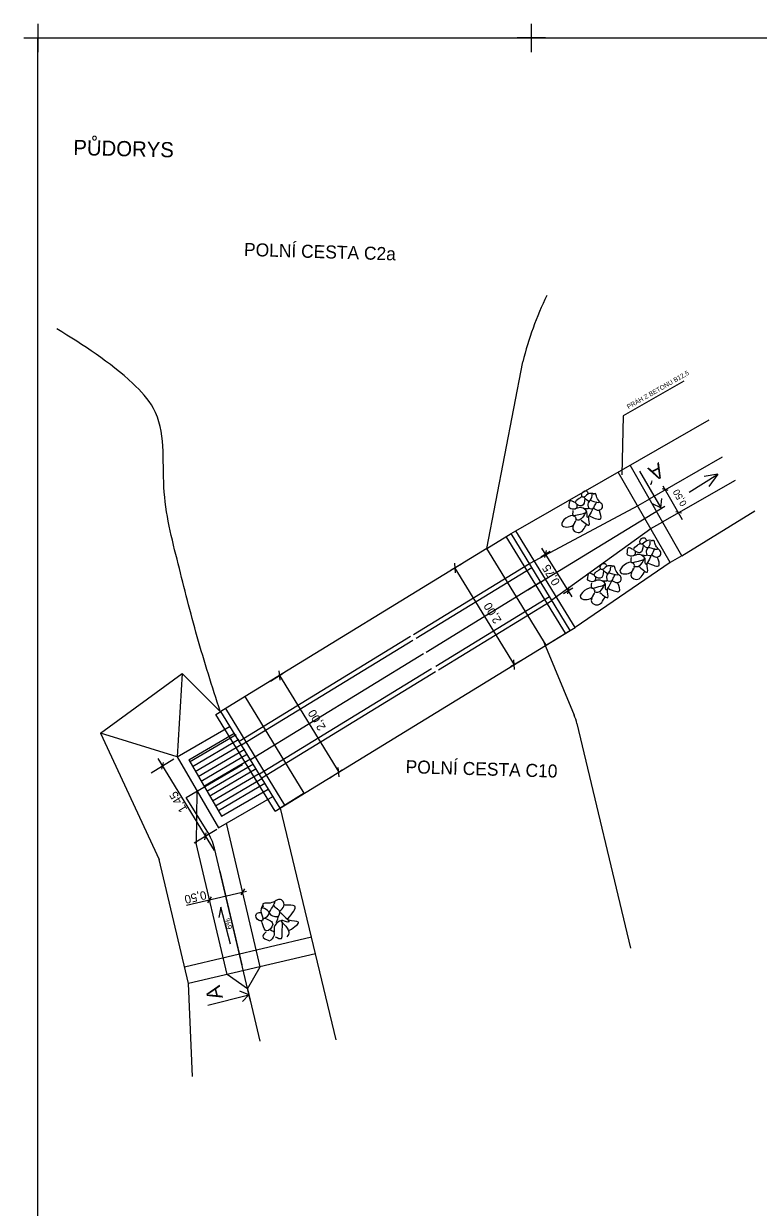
# Model space of a CAD drawing. Extents: x -463095.2 to -463031, y -1105061.3 to -1104976.3.
# Drawn here: x -463091.37 to -463065.46, y -1105018.06 to -1104976.31 of the extents above; entities that cross this region are included whole.
import ezdxf

# ---------------------------------------------------------------- set-up
doc = ezdxf.new("R2010")
doc.units = 0
for name, color, linetype in [('Implicitní', 7, 'Continuous'), ('Vrstva 14', 7, 'Continuous'), ('Vrstva 57', 7, 'Continuous')]:
    doc.layers.add(name, color=color, linetype=linetype)

msp = doc.modelspace()

# ---------------------------------------------------------------- linework, layer by layer
at = {"layer": 'Implicitní'}
for p, q in [((-463073.467, -1104976.311), (-463073.467, -1104977.311)), ((-463073.467, -1104976.311), (-463073.467, -1104977.311)), ((-463073.467, -1104976.312), (-463073.467, -1104977.312)), ((-463073.467, -1104976.312), (-463073.467, -1104977.312)), ((-463072.967, -1104976.811), (-463073.967, -1104976.811)), ((-463072.967, -1104976.811), (-463073.967, -1104976.811)), ((-463072.967, -1104976.812), (-463073.967, -1104976.812)), ((-463072.967, -1104976.812), (-463073.967, -1104976.812))]:
    msp.add_line(p, q, dxfattribs=at)
at = {"layer": 'Vrstva 14'}
for p, q in [((-463090.867, -1104976.311), (-463090.867, -1104977.311)), ((-463090.867, -1104976.312), (-463090.867, -1104977.312)), ((-463090.867, -1104976.312), (-463090.867, -1104977.312)), ((-463091.367, -1104976.811), (-463090.367, -1104976.811)), ((-463091.367, -1104976.812), (-463090.367, -1104976.812)), ((-463091.367, -1104976.812), (-463090.367, -1104976.812)), ((-463075.036, -1104994.821), (-463073.77, -1104988.236)), ((-463068.091, -1104988.92), (-463070.232, -1104990.146)), ((-463070.232, -1104990.146), (-463070.28, -1104992.219)), ((-463074.013, -1104994.194), (-463067.196, -1104990.29)), ((-463069.301, -1104993.076), (-463066.73, -1104991.595)), ((-463068.574, -1104995.32), (-463070.403, -1104992.127)), ((-463068.157, -1104995.081), (-463069.987, -1104991.888)), ((-463067.903, -1104992.83), (-463066.894, -1104992.206)), ((-463066.894, -1104992.206), (-463067.377, -1104992.28)), ((-463066.894, -1104992.206), (-463067.208, -1104992.63)), ((-463068.842, -1104993.886), (-463066.262, -1104992.412)), ((-463068.827, -1104992.607), (-463068.143, -1104993.801)), ((-463068.906, -1104993.389), (-463068.87, -1104993.054)), ((-463068.645, -1104992.771), (-463068.836, -1104992.718)), ((-463069.714, -1104993.315), (-463073.521, -1104995.347)), ((-463069.297, -1104993.077), (-463069.714, -1104993.315)), ((-463068.843, -1104993.889), (-463069.26, -1104994.127)), ((-463068.176, -1104993.579), (-463068.367, -1104993.526)), ((-463068.157, -1104995.081), (-463065.582, -1104993.499)), ((-463075.036, -1104994.821), (-463074.183, -1104994.299)), ((-463074.183, -1104994.299), (-463074.013, -1104994.194)), ((-463072.093, -1104997.709), (-463074.183, -1104994.299)), ((-463071.923, -1104997.605), (-463074.013, -1104994.194)), ((-463069.252, -1104994.123), (-463072.748, -1104996.647)), ((-463072.264, -1104997.814), (-463074.354, -1104994.403)), ((-463075.036, -1104994.821), (-463083.563, -1105000.046)), ((-463072.946, -1104998.232), (-463075.036, -1104994.821)), ((-463073.132, -1104995.117), (-463072.802, -1104994.913)), ((-463072.032, -1104996.532), (-463073.093, -1104994.815)), ((-463072.949, -1104994.895), (-463073.004, -1104995.137)), ((-463068.157, -1104995.081), (-463068.574, -1104995.32)), ((-463077.618, -1104997.858), (-463073.535, -1104995.356)), ((-463077.526, -1104997.989), (-463073.452, -1104995.492)), ((-463075.931, -1104995.37), (-463076.291, -1104995.59)), ((-463076.178, -1104995.345), (-463076.149, -1104995.679)), ((-463076.163, -1104995.512), (-463074.073, -1104998.923)), ((-463068.574, -1104995.32), (-463071.923, -1104997.605)), ((-463077.18, -1104998.481), (-463073.138, -1104996.004)), ((-463072.333, -1104996.41), (-463072.003, -1104996.206)), ((-463072.14, -1104996.178), (-463072.196, -1104996.419)), ((-463076.836, -1104998.973), (-463072.825, -1104996.516)), ((-463076.744, -1104999.105), (-463072.741, -1104996.652)), ((-463072.093, -1104997.709), (-463071.923, -1104997.605)), ((-463077.731, -1104997.927), (-463083.767, -1105001.626)), ((-463077.647, -1104998.063), (-463083.684, -1105001.762)), ((-463082.496, -1105004.084), (-463072.085, -1104997.704)), ((-463072.946, -1104998.232), (-463072.093, -1104997.709)), ((-463073.024, -1104998.124), (-463071.957, -1105000.697)), ((-463077.274, -1104998.538), (-463083.37, -1105002.274)), ((-463073.841, -1104998.78), (-463074.201, -1104999.001)), ((-463074.059, -1104999.09), (-463074.088, -1104998.755)), ((-463088.659, -1105001.332), (-463085.777, -1104999.23)), ((-463085.777, -1104999.23), (-463085.957, -1105002.169)), ((-463084.438, -1105000.57), (-463085.777, -1104999.23)), ((-463076.989, -1104999.067), (-463083.057, -1105002.785)), ((-463076.846, -1104999.167), (-463082.973, -1105002.922)), ((-463082.667, -1104999.497), (-463082.222, -1104999.224)), ((-463082.365, -1104999.136), (-463082.336, -1104999.47)), ((-463082.35, -1104999.303), (-463080.26, -1105002.714)), ((-463083.563, -1105000.046), (-463084.415, -1105000.568)), ((-463081.473, -1105003.456), (-463083.563, -1105000.046)), ((-463084.586, -1105000.673), (-463084.415, -1105000.568)), ((-463082.325, -1105003.979), (-463084.415, -1105000.568)), ((-463082.155, -1105003.874), (-463084.245, -1105000.464)), ((-463082.496, -1105004.083), (-463084.586, -1105000.673)), ((-463071.859, -1105000.999), (-463069.969, -1105008.921)), ((-463088.659, -1105001.332), (-463086.589, -1105005.788)), ((-463085.957, -1105002.169), (-463088.659, -1105001.332)), ((-463085.957, -1105002.169), (-463084.085, -1105001.084)), ((-463085.547, -1105002.278), (-463083.952, -1105001.353)), ((-463083.878, -1105001.39), (-463085.519, -1105002.357)), ((-463083.777, -1105001.563), (-463085.417, -1105002.529)), ((-463083.675, -1105001.735), (-463085.316, -1105002.702)), ((-463086.074, -1105002.258), (-463086.873, -1105002.747)), ((-463086.642, -1105002.23), (-463084.653, -1105005.477)), ((-463085.957, -1105002.169), (-463084.502, -1105004.678)), ((-463083.574, -1105001.907), (-463085.214, -1105002.874)), ((-463083.472, -1105002.08), (-463085.113, -1105003.046)), ((-463083.371, -1105002.252), (-463085.011, -1105003.219)), ((-463086.496, -1105002.607), (-463086.439, -1105002.366)), ((-463085.547, -1105002.278), (-463084.393, -1105004.268)), ((-463083.269, -1105002.424), (-463084.91, -1105003.391)), ((-463083.167, -1105002.596), (-463084.808, -1105003.563)), ((-463080.577, -1105002.908), (-463080.132, -1105002.635)), ((-463080.246, -1105002.881), (-463080.275, -1105002.546)), ((-463083.066, -1105002.769), (-463084.706, -1105003.736)), ((-463082.964, -1105002.941), (-463084.605, -1105003.908)), ((-463082.863, -1105003.113), (-463084.503, -1105004.08)), ((-463084.393, -1105004.268), (-463082.745, -1105003.312)), ((-463081.473, -1105003.456), (-463082.325, -1105003.979)), ((-463084.502, -1105004.678), (-463082.587, -1105003.567)), ((-463082.496, -1105004.083), (-463082.325, -1105003.979)), ((-463082.329, -1105003.983), (-463080.355, -1105012.151)), ((-463084.559, -1105004.73), (-463085.357, -1105005.219)), ((-463084.985, -1105005.096), (-463084.928, -1105004.855)), ((-463083.367, -1105010.789), (-463084.644, -1105005.396)), ((-463083.661, -1105009.504), (-463084.435, -1105006.208)), ((-463083.582, -1105006.829), (-463083.714, -1105007.039)), ((-463085.623, -1105007.407), (-463083.516, -1105006.912)), ((-463084.759, -1105007.112), (-463084.89, -1105007.322)), ((-463081.218, -1105008.531), (-463085.696, -1105009.584)), ((-463081.081, -1105009.117), (-463085.559, -1105010.17)), ((-463083.43, -1105010.56), (-463083.744, -1105010.437)), ((-463083.47, -1105010.349), (-463083.043, -1105012.2))]:
    msp.add_line(p, q, dxfattribs=at)
msp.add_lwpolyline([(-463090.867, -1105060.811), (-463090.867, -1104976.812), (-463031.467, -1104976.812), (-463031.467, -1105060.811)], close=True, dxfattribs=at)
for points in [[(-463069.649, -1104992.092), (-463068.906, -1104993.389), (-463069.199, -1104993.243)], [(-463073.59, -1104996.283), (-463068.761, -1104993.331)], [(-463084.894, -1105004.797), (-463085.635, -1105003.611), (-463083.657, -1105002.446)], [(-463085.262, -1105003.375), (-463085.259, -1105003.378), (-463085.284, -1105005.221)], [(-463083.47, -1105010.349), (-463083.027, -1105009.576), (-463084.218, -1105004.512)], [(-463083.47, -1105010.349), (-463084.195, -1105009.845), (-463085.284, -1105005.221)], [(-463085.419, -1105013.452), (-463085.559, -1105010.17), (-463086.589, -1105005.788)], [(-463084.075, -1105008.775), (-463084.415, -1105007.469), (-463084.487, -1105007.843)], [(-463084.877, -1105010.935), (-463083.43, -1105010.56), (-463083.648, -1105010.804)]]:
    msp.add_lwpolyline(points, dxfattribs=at)
for centre, radius, start, end in [((-463061.322, -1104991.416), 12.848, 154.5646, 165.6667), ((-463073.805, -1105001.463), 2, 13.4219, 22.5132), ((-463086.59, -1105005.857), 2, 13.3222, 31.992)]:
    msp.add_arc(centre, radius, start, end, dxfattribs=at)
for points in [[(-463084.438, -1105000.57), (-463085.247, -1104997.939), (-463085.919, -1104995.363), (-463086.422, -1104992.659), (-463086.79, -1104989.879), (-463087.515, -1104989.004), (-463090.196, -1104987.076)], [(-463071.579, -1104993.056), (-463071.691, -1104993.318), (-463071.909, -1104993.202), (-463071.778, -1104993.05), (-463071.676, -1104992.981)], [(-463071.237, -1104992.893), (-463071.47, -1104992.907), (-463071.65, -1104993.01), (-463071.693, -1104992.915), (-463071.536, -1104992.791), (-463071.458, -1104992.889)], [(-463071.625, -1104992.996), (-463071.405, -1104993.132), (-463071.326, -1104992.967), (-463071.325, -1104992.911)], [(-463071.389, -1104993.122), (-463071.064, -1104993.176), (-463071.154, -1104993.021), (-463071.208, -1104992.887), (-463071.291, -1104992.913)], [(-463071.943, -1104993.2), (-463072.086, -1104993.14), (-463072.149, -1104993.371)], [(-463071.857, -1104993.293), (-463071.88, -1104993.404), (-463072.078, -1104993.419), (-463072.144, -1104993.38)], [(-463071.999, -1104993.483), (-463071.992, -1104993.665), (-463071.854, -1104993.639), (-463071.527, -1104993.508), (-463071.696, -1104993.384), (-463071.884, -1104993.417)], [(-463071.289, -1104993.393), (-463071.499, -1104993.709), (-463071.509, -1104993.519), (-463071.755, -1104993.811), (-463071.904, -1104993.799)], [(-463071.602, -1104993.397), (-463071.441, -1104993.392), (-463071.464, -1104993.296), (-463071.401, -1104993.14)], [(-463071.469, -1104993.393), (-463071.267, -1104993.392), (-463071.234, -1104993.318), (-463071.153, -1104993.173)], [(-463071.406, -1104993.683), (-463071.017, -1104993.767), (-463071.069, -1104993.49)], [(-463071.277, -1104993.392), (-463071.102, -1104993.471), (-463070.96, -1104993.378), (-463070.965, -1104993.272), (-463071.073, -1104993.177)], [(-463071.876, -1104993.772), (-463071.952, -1104993.671), (-463072.394, -1104993.997), (-463071.996, -1104994.003), (-463071.913, -1104993.865)], [(-463071.894, -1104993.836), (-463071.985, -1104994.177), (-463071.813, -1104994.258), (-463071.516, -1104993.962)], [(-463071.709, -1104993.818), (-463071.422, -1104993.993), (-463071.439, -1104993.719), (-463071.43, -1104993.658)], [(-463069.526, -1104994.71), (-463069.638, -1104994.971), (-463069.855, -1104994.856), (-463069.724, -1104994.704), (-463069.622, -1104994.634)], [(-463069.184, -1104994.547), (-463069.416, -1104994.56), (-463069.596, -1104994.664), (-463069.64, -1104994.569), (-463069.482, -1104994.445), (-463069.404, -1104994.542)], [(-463069.571, -1104994.649), (-463069.351, -1104994.785), (-463069.273, -1104994.62), (-463069.272, -1104994.564)], [(-463069.335, -1104994.776), (-463069.011, -1104994.83), (-463069.1, -1104994.674), (-463069.154, -1104994.541), (-463069.237, -1104994.567)], [(-463069.889, -1104994.854), (-463070.033, -1104994.794), (-463070.095, -1104995.025)], [(-463069.803, -1104994.946), (-463069.826, -1104995.057), (-463070.024, -1104995.073), (-463070.091, -1104995.033)], [(-463069.945, -1104995.136), (-463069.938, -1104995.319), (-463069.8, -1104995.293), (-463069.474, -1104995.161), (-463069.642, -1104995.038), (-463069.83, -1104995.07)], [(-463069.235, -1104995.047), (-463069.445, -1104995.362), (-463069.456, -1104995.173), (-463069.701, -1104995.465), (-463069.851, -1104995.453)], [(-463069.548, -1104995.051), (-463069.387, -1104995.045), (-463069.41, -1104994.95), (-463069.347, -1104994.794)], [(-463069.416, -1104995.047), (-463069.213, -1104995.045), (-463069.18, -1104994.971), (-463069.099, -1104994.827)], [(-463069.353, -1104995.337), (-463068.964, -1104995.421), (-463069.015, -1104995.144)], [(-463069.223, -1104995.045), (-463069.048, -1104995.124), (-463068.906, -1104995.032), (-463068.911, -1104994.926), (-463069.019, -1104994.831)], [(-463070.923, -1104995.61), (-463071.035, -1104995.872), (-463071.252, -1104995.757), (-463071.122, -1104995.605), (-463071.02, -1104995.535)], [(-463070.581, -1104995.448), (-463070.813, -1104995.461), (-463070.994, -1104995.564), (-463071.037, -1104995.469), (-463070.879, -1104995.346), (-463070.801, -1104995.443)], [(-463070.969, -1104995.55), (-463070.749, -1104995.686), (-463070.67, -1104995.521), (-463070.669, -1104995.465)], [(-463070.732, -1104995.676), (-463070.408, -1104995.73), (-463070.497, -1104995.575), (-463070.551, -1104995.442), (-463070.634, -1104995.467)], [(-463069.822, -1104995.425), (-463069.898, -1104995.325), (-463070.34, -1104995.65), (-463069.942, -1104995.656), (-463069.859, -1104995.518)], [(-463069.841, -1104995.489), (-463069.931, -1104995.831), (-463069.759, -1104995.911), (-463069.462, -1104995.616)], [(-463069.655, -1104995.472), (-463069.369, -1104995.647), (-463069.386, -1104995.373), (-463069.376, -1104995.312)], [(-463071.287, -1104995.754), (-463071.43, -1104995.694), (-463071.493, -1104995.926)], [(-463071.201, -1104995.847), (-463071.224, -1104995.958), (-463071.421, -1104995.973), (-463071.488, -1104995.934)], [(-463071.343, -1104996.037), (-463071.336, -1104996.219), (-463071.198, -1104996.194), (-463070.871, -1104996.062), (-463071.039, -1104995.939), (-463071.227, -1104995.971)], [(-463070.632, -1104995.947), (-463070.842, -1104996.263), (-463070.853, -1104996.074), (-463071.099, -1104996.366), (-463071.248, -1104996.353)], [(-463070.945, -1104995.951), (-463070.784, -1104995.946), (-463070.808, -1104995.85), (-463070.744, -1104995.694)], [(-463070.813, -1104995.948), (-463070.611, -1104995.946), (-463070.578, -1104995.872), (-463070.496, -1104995.728)], [(-463070.62, -1104995.946), (-463070.446, -1104996.025), (-463070.304, -1104995.932), (-463070.309, -1104995.827), (-463070.417, -1104995.732)], [(-463071.219, -1104996.326), (-463071.295, -1104996.226), (-463071.738, -1104996.551), (-463071.34, -1104996.557), (-463071.256, -1104996.419)], [(-463071.238, -1104996.39), (-463071.328, -1104996.731), (-463071.157, -1104996.812), (-463070.86, -1104996.516)], [(-463071.053, -1104996.372), (-463070.766, -1104996.548), (-463070.783, -1104996.273), (-463070.774, -1104996.213)], [(-463070.75, -1104996.238), (-463070.361, -1104996.321), (-463070.413, -1104996.045)], [(-463082.349, -1105007.618), (-463082.193, -1105007.437), (-463082.253, -1105007.234), (-463082.381, -1105007.202), (-463082.534, -1105007.298)], [(-463082.932, -1105007.393), (-463082.999, -1105007.676), (-463082.94, -1105007.929), (-463083.069, -1105007.947), (-463083.161, -1105007.714), (-463083.016, -1105007.656)], [(-463082.948, -1105007.894), (-463082.707, -1105007.679), (-463082.876, -1105007.526), (-463082.943, -1105007.505)], [(-463082.712, -1105007.656), (-463082.532, -1105007.287), (-463082.75, -1105007.338), (-463082.929, -1105007.356), (-463082.928, -1105007.464)], [(-463082.459, -1105008.009), (-463082.408, -1105007.815), (-463082.531, -1105007.808), (-463082.695, -1105007.677)], [(-463082.416, -1105007.849), (-463082.346, -1105007.607), (-463082.423, -1105007.541), (-463082.567, -1105007.392)], [(-463082.352, -1105007.633), (-463082.049, -1105007.997), (-463082.279, -1105007.942), (-463082.017, -1105008.341), (-463082.085, -1105008.515)], [(-463082.046, -1105007.877), (-463081.807, -1105007.441), (-463082.157, -1105007.404)], [(-463082.859, -1105007.861), (-463082.586, -1105008.089), (-463082.802, -1105008.308), (-463082.937, -1105008.097), (-463082.984, -1105007.95)], [(-463082.498, -1105008.516), (-463082.277, -1105008.573), (-463082.258, -1105008.398), (-463082.3, -1105007.96), (-463082.507, -1105008.117), (-463082.536, -1105008.354)], [(-463081.993, -1105008.288), (-463081.681, -1105008.007), (-463082.015, -1105007.93), (-463082.085, -1105007.897)], [(-463082.817, -1105008.348), (-463082.94, -1105008.498), (-463082.685, -1105008.656)], [(-463082.675, -1105008.278), (-463082.55, -1105008.345), (-463082.602, -1105008.587), (-463082.673, -1105008.653)]]:
    msp.add_spline(points, degree=3, dxfattribs=at)

# ---------------------------------------------------------------- texts
for s, height, rotation, p in [('PŮDORYS', 0.536, 358.5898, (-463089.622, -1104980.942)), ('A´', 0.536, 207.7449, (-463068.967, -1104991.774)), ('0,50', 0.24, 119.8041, (-463067.973, -1104993.246)), ('0,75', 0.3, 121.7127, (-463072.439, -1104996.014)), ('2,00', 0.3, 121.4976, (-463074.505, -1104997.357)), ('2,00', 0.3, 121.4976, (-463080.702, -1105001.131)), ('1,45', 0.3, 121.4976, (-463085.586, -1105004.022)), ('0,50', 0.3, 193.229, (-463084.963, -1105006.892)), ('A', 0.536, 104.5585, (-463084.338, -1105010.665))]:
    msp.add_text(s, height=height, rotation=rotation, dxfattribs=at).set_placement(p)
at = {"layer": 'Vrstva 57'}
for s, height, rotation, p in [('POLNÍ CESTA C2a', 0.459, 358.2755, (-463083.603, -1104984.501)), ('PRÁH Z BETONU B12,5', 0.1632, 29.8041, (-463070.039, -1104989.91)), ('POLNÍ CESTA C10', 0.459, 358.2755, (-463077.905, -1105002.744)), ('6%', 0.204, 104.5585, (-463084.004, -1105008.23))]:
    msp.add_text(s, height=height, rotation=rotation, dxfattribs=at).set_placement(p)

doc.saveas('drawing.dxf')
